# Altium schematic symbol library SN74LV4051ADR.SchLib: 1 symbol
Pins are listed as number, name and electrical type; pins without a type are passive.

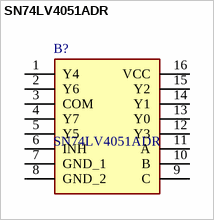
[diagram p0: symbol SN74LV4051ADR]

## SN74LV4051ADR
designator B?
8-Channel Analog Multiplexer/Demultiplexer; Manufacturer_Name: Texas Instruments; Geometry.Height: 1.75mm
footprint SOIC127P600X175-16N
pins: 1 Y4, 2 Y6, 3 COM, 4 Y7, 5 Y5, 6 INH, 7 GND_1, 8 GND_2, 9 C, 10 B, 11 A, 12 Y3, 13 Y0, 14 Y1, 15 Y2, 16 VCC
